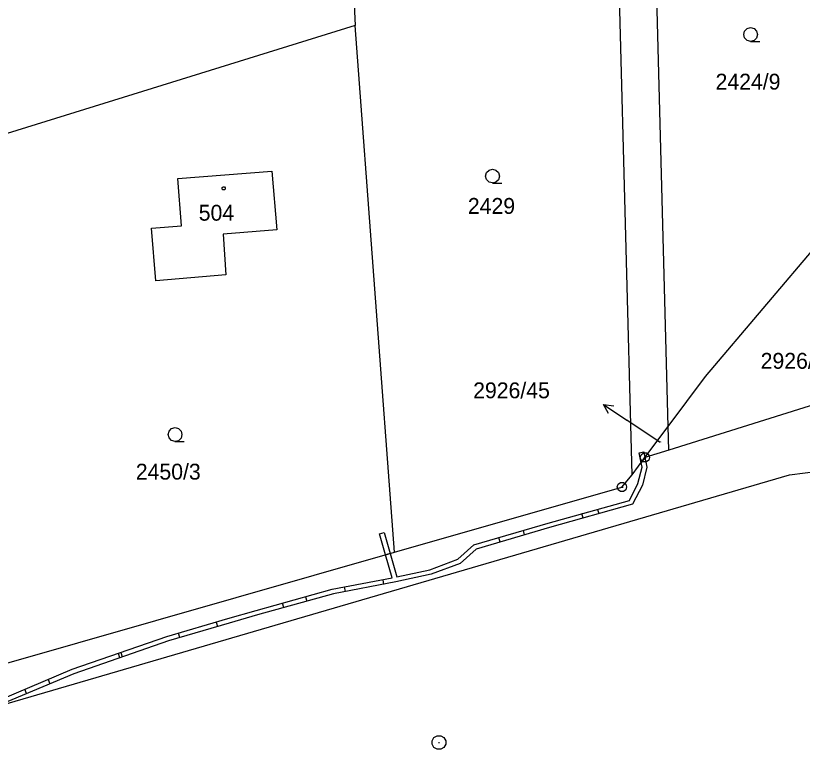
# Model space of a CAD drawing. Extents: x -760611 to -758411, y -1176479 to -1174807.
# Drawn here: x -759061.6 to -758977.4, y -1175107.9 to -1175029.4 of the extents above; entities that cross this region are included whole.
import ezdxf

# ---------------------------------------------------------------- set-up
doc = ezdxf.new("R2010")
doc.units = 0
for name, color, linetype in [('1', 7, 'Continuous'), ('12', 7, 'Continuous'), ('13', 7, 'Continuous'), ('2', 7, 'Continuous'), ('3', 7, 'Continuous'), ('5', 7, 'Continuous'), ('7', 7, 'Continuous'), ('8', 7, 'Continuous')]:
    doc.layers.add(name, color=color, linetype=linetype)

msp = doc.modelspace()

# ---------------------------------------------------------------- linework, layer by layer
at = {"layer": '1'}
for p, q in [((-759027.14, -1174996.19), (-759025.28, -1175030.41)), ((-758995.64, -1175078.53), (-758997.14, -1175020.68)), ((-758991.77, -1175073.34), (-758993.13, -1175021.18)), ((-759025.28, -1175030.41), (-759067.85, -1175043.58)), ((-759021.09, -1175086.81), (-759025.28, -1175030.41)), ((-759044.28, -1175046.77), (-759034.22, -1175045.98)), ((-759034.22, -1175045.98), (-759033.69, -1175052.29)), ((-759043.88, -1175051.84), (-759044.28, -1175046.77)), ((-758987.78, -1175067.99), (-758972.45, -1175049.88)), ((-759047.1, -1175052.09), (-759043.88, -1175051.84)), ((-759046.66, -1175057.74), (-759047.1, -1175052.09)), ((-759033.69, -1175052.29), (-759039.44, -1175052.76)), ((-759039.44, -1175052.76), (-759039.15, -1175057.11)), ((-759039.15, -1175057.11), (-759046.66, -1175057.74)), ((-758991.77, -1175073.34), (-758987.78, -1175067.99)), ((-758968.55, -1175068.63), (-758991.71, -1175075.87)), ((-758994.25, -1175076.66), (-758991.77, -1175073.34)), ((-758991.71, -1175075.87), (-758991.77, -1175073.34)), ((-758991.71, -1175075.87), (-758994.25, -1175076.66)), ((-758978.79, -1175078.51), (-758953.53, -1175075.25)), ((-758995.64, -1175078.53), (-758994.25, -1175076.66)), ((-759063.16, -1175103.17), (-758978.79, -1175078.51)), ((-758996.72, -1175079.83), (-758995.64, -1175078.53)), ((-759021.09, -1175086.81), (-758996.72, -1175079.83)), ((-759064.59, -1175099.26), (-759021.09, -1175086.81))]:
    msp.add_line(p, q, dxfattribs=at)
at = {"layer": '12'}
for p, q in [((-759044.28, -1175046.77), (-759034.22, -1175045.98)), ((-759034.22, -1175045.98), (-759033.69, -1175052.29)), ((-759043.88, -1175051.84), (-759044.28, -1175046.77)), ((-759047.1, -1175052.09), (-759043.88, -1175051.84)), ((-759046.66, -1175057.74), (-759047.1, -1175052.09)), ((-759033.69, -1175052.29), (-759039.44, -1175052.76)), ((-759039.44, -1175052.76), (-759039.15, -1175057.11)), ((-759039.15, -1175057.11), (-759046.66, -1175057.74))]:
    msp.add_line(p, q, dxfattribs=at)
at = {"layer": '13'}
for p, q in [((-758994.66, -1175077.22), (-758994.25, -1175076.66)), ((-758994.25, -1175076.66), (-758994.05, -1175077.69)), ((-758994.57, -1175077.69), (-758994.66, -1175077.22)), ((-758995, -1175079.43), (-758994.57, -1175077.69)), ((-758994.05, -1175077.69), (-758994.52, -1175079.61)), ((-758995.92, -1175081.25), (-758995, -1175079.43)), ((-758994.52, -1175079.61), (-758995.58, -1175081.67)), ((-759004.63, -1175083.68), (-758995.92, -1175081.25)), ((-758995.58, -1175081.67), (-759004.49, -1175084.16)), ((-759000.877, -1175083.15), (-759001.012, -1175082.669)), ((-758999.332, -1175082.202), (-758999.198, -1175082.684)), ((-759012.59, -1175086.03), (-759004.63, -1175083.68)), ((-759004.49, -1175084.16), (-759012.33, -1175086.47)), ((-759009.766, -1175085.714), (-759009.907, -1175085.235)), ((-759007.315, -1175084.473), (-759007.174, -1175084.952)), ((-759014.3, -1175087.56), (-759012.59, -1175086.03)), ((-759012.33, -1175086.47), (-759014.04, -1175088)), ((-759022.03, -1175087.08), (-759021.54, -1175086.94)), ((-759021.32, -1175089.56), (-759022.03, -1175087.08)), ((-759021.54, -1175086.94), (-759020.82, -1175089.46)), ((-759017.28, -1175088.68), (-759014.3, -1175087.56)), ((-759014.04, -1175088), (-759017.14, -1175089.16)), ((-759017.14, -1175089.16), (-759020.93, -1175089.99)), ((-759020.82, -1175089.46), (-759017.28, -1175088.68)), ((-759027.75, -1175090.78), (-759021.32, -1175089.56)), ((-759020.93, -1175089.99), (-759027.63, -1175091.27)), ((-759022.346, -1175089.755), (-759022.253, -1175090.246)), ((-759035.9, -1175093.04), (-759027.75, -1175090.78)), ((-759026.332, -1175091.022), (-759026.426, -1175090.531)), ((-759027.63, -1175091.27), (-759035.76, -1175093.52)), ((-759030.6, -1175091.57), (-759030.466, -1175092.052)), ((-759032.931, -1175092.737), (-759033.064, -1175092.255)), ((-759038.92, -1175093.92), (-759035.9, -1175093.04)), ((-759035.76, -1175093.52), (-759038.78, -1175094.4)), ((-759045.47, -1175095.85), (-759038.92, -1175093.92)), ((-759038.78, -1175094.4), (-759045.29, -1175096.31)), ((-759040.194, -1175094.295), (-759040.053, -1175094.775)), ((-759055.6, -1175099.34), (-759045.47, -1175095.85)), ((-759044.058, -1175095.948), (-759044.198, -1175095.469)), ((-759045.29, -1175096.31), (-759055.42, -1175099.82)), ((-759050.487, -1175098.111), (-759050.651, -1175097.638)), ((-759050.4, -1175097.548), (-759050.237, -1175098.021)), ((-759063.25, -1175102.57), (-759055.6, -1175099.34)), ((-759055.42, -1175099.82), (-759063.18, -1175103.07)), ((-759058.183, -1175100.431), (-759057.988, -1175100.891)), ((-759060.493, -1175101.945), (-759060.686, -1175101.483))]:
    msp.add_line(p, q, dxfattribs=at)
for points in [[(-758994.66, -1175077.22), (-758994.87, -1175076.15), (-758994.38, -1175076.05)], [(-758994.38, -1175076.05), (-758994.25, -1175076.66), (-758994.66, -1175077.22)]]:
    msp.add_lwpolyline(points, dxfattribs=at)
msp.add_lwpolyline([(-759022.03, -1175087.08), (-759022.67, -1175084.82), (-759022.19, -1175084.68), (-759021.54, -1175086.94)], close=True, dxfattribs=at)
at = {"layer": '3'}
for points in [[(-758982.93, -1175032.1), (-758983.31, -1175032), (-758983.58, -1175031.73), (-758983.68, -1175031.36), (-758983.58, -1175030.99), (-758983.31, -1175030.72), (-758982.94, -1175030.62), (-758982.57, -1175030.72), (-758982.3, -1175030.99), (-758982.2, -1175031.37), (-758982.3, -1175031.75), (-758982.57, -1175032.02), (-758982.95, -1175032.12), (-758981.95, -1175032.12)], [(-759010.57, -1175047.26), (-759010.95, -1175047.16), (-759011.22, -1175046.89), (-759011.32, -1175046.52), (-759011.22, -1175046.15), (-759010.95, -1175045.88), (-759010.58, -1175045.78), (-759010.21, -1175045.88), (-759009.94, -1175046.15), (-759009.84, -1175046.53), (-759009.94, -1175046.91), (-759010.21, -1175047.18), (-759010.59, -1175047.28), (-759009.59, -1175047.28)], [(-759044.57, -1175074.94), (-759044.95, -1175074.84), (-759045.22, -1175074.57), (-759045.32, -1175074.2), (-759045.22, -1175073.83), (-759044.95, -1175073.56), (-759044.58, -1175073.46), (-759044.21, -1175073.56), (-759043.94, -1175073.83), (-759043.84, -1175074.21), (-759043.94, -1175074.59), (-759044.21, -1175074.86), (-759044.59, -1175074.96), (-759043.59, -1175074.96)]]:
    msp.add_lwpolyline(points, dxfattribs=at)
at = {"layer": '5'}
msp.add_lwpolyline([(-759039.37, -1175047.67), (-759039.27, -1175047.69), (-759039.22, -1175047.78), (-759039.2, -1175047.84), (-759039.22, -1175047.93), (-759039.3, -1175048), (-759039.37, -1175048.01), (-759039.46, -1175047.98), (-759039.52, -1175047.92), (-759039.54, -1175047.84), (-759039.52, -1175047.75), (-759039.44, -1175047.68)], close=True, dxfattribs=at)
at = {"layer": '7'}
for p in [(-758998.705, -1175070.994), (-758992.63, -1175075.05)]:
    msp.add_line(p, (-758996.21, -1175072.66), dxfattribs=at)
msp.add_lwpolyline([(-758998.151, -1175071.965), (-758998.705, -1175070.994), (-758997.596, -1175071.133)], dxfattribs=at)
at = {"layer": '8'}
for p, q in [((-758994.37, -1175076.66), (-758994.13, -1175076.66)), ((-758996.84, -1175079.83), (-758996.6, -1175079.83)), ((-759016.36, -1175107.18), (-759016.26, -1175107.18))]:
    msp.add_line(p, q, dxfattribs=at)
for points in [[(-758994.1, -1175076.18), (-758993.85, -1175076.36), (-758993.75, -1175076.65), (-758993.85, -1175076.94), (-758994.1, -1175077.12), (-758994.41, -1175077.12), (-758994.66, -1175076.94), (-758994.76, -1175076.65), (-758994.66, -1175076.36), (-758994.41, -1175076.18)], [(-758996.57, -1175079.35), (-758996.32, -1175079.53), (-758996.22, -1175079.82), (-758996.32, -1175080.11), (-758996.57, -1175080.29), (-758996.88, -1175080.29), (-758997.13, -1175080.11), (-758997.23, -1175079.82), (-758997.13, -1175079.53), (-758996.88, -1175079.35)], [(-759016.12, -1175106.46), (-759015.78, -1175106.65), (-759015.59, -1175106.99), (-759015.59, -1175107.38), (-759015.78, -1175107.72), (-759016.12, -1175107.91), (-759016.51, -1175107.91), (-759016.85, -1175107.72), (-759017.04, -1175107.38), (-759017.04, -1175106.99), (-759016.85, -1175106.65), (-759016.51, -1175106.46)]]:
    msp.add_lwpolyline(points, close=True, dxfattribs=at)

# ---------------------------------------------------------------- texts
at = {"layer": '2'}
for s, height, p in [('2424/9', 1.7, (-758986.69, -1175037.26)), ('2429', 1.7, (-759013.221, -1175050.57)), ('504', 1.7, (-759042.048, -1175051.3)), ('2926/28', 1.7, (-758981.863, -1175067.16)), ('2926/45', 0.1, (-758992.924, -1175075.05)), ('2450/3', 1.7, (-759048.787, -1175079.03))]:
    msp.add_text(s, height=height, dxfattribs=at).set_placement(p)
at = {"layer": '7'}
msp.add_text('2926/45', height=1.7, dxfattribs=at).set_placement((-759012.656, -1175070.32))

doc.saveas('drawing.dxf')
